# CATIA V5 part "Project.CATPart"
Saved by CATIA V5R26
Part number: Project
Bounding box of the stored display mesh (mm): x -379.025 to 257.653, y 0 to 550.967, z -174.504 to 392.31
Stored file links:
  D:\LinkedIn Learning\NURBS\CATIA\Class Parts\Project.CATPart
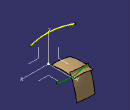
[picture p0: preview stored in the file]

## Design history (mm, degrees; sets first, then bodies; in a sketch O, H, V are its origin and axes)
AxisSystem1: origin (0, 0, 0), X (1, 0, 0), Y (0, 1, 0), Z (0, 0, 1)
Set1
  DatumSurface1
  DatumSurface2
  St3DCurveFeature1 "CATSt3DCurveFeatureName": Order 6, CreationType 1, ClosureMode false, ConstructionPoints ({point type Coord, X -267.3218, Y 276.8681, Z 0}; {point type Coord, X -12.3983, Y 377.3344, Z 0}; {point type Coord, X 176.2624, Y 299.6682, Z 0}), SymmetryMode false
  St3DCurveFeature2 "CATSt3DCurveFeatureName": Order 6, CreationType 1, ClosureMode false, ConstructionPoints ({point type Coord, X 257.6527, Y 0, Z 353.6812}; {point type Coord, X 4.5467, Y 0, Z 447.8526}; {point type Coord, X -379.0254, Y 0, Z 312.4529}), SymmetryMode false
Body1 (main body)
